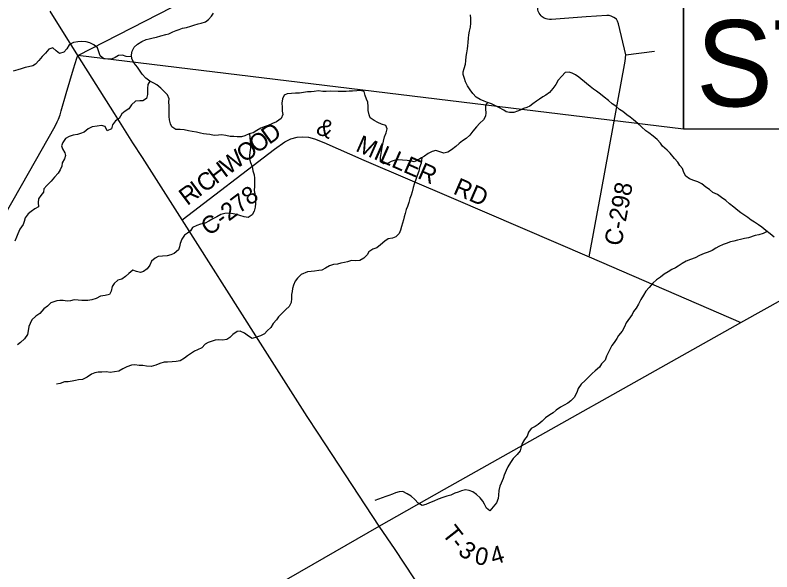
# Model space of a CAD drawing. Extents: x 0 to 34, y 0 to 22.
# Drawn here: x 5.216 to 6.445, y 18.969 to 19.874 of the extents above; entities that cross this region are included whole.
import ezdxf

# ---------------------------------------------------------------- set-up
doc = ezdxf.new("R2010")
doc.units = 0
for name, color, linetype in [('GM_X_County_Road', 7, 'Continuous'), ('GM_X_County_Road_Text', 7, 'Continuous'), ('GM_X_Minor_River', 7, 'Continuous'), ('GM_X_State_Route', 7, 'Continuous'), ('GM_X_Township_Road_Text', 7, 'Continuous'), ('SH_Text', 7, 'Continuous')]:
    doc.layers.add(name, color=color, linetype=linetype)

msp = doc.modelspace()

# ---------------------------------------------------------------- linework, layer by layer
at = {"layer": 'GM_X_County_Road'}
msp.add_line((6.2081, 19.8092), (6.2546, 19.8149), dxfattribs=at)
for points in [[(6.2081, 19.8092), (6.1961, 19.8595), (6.1942, 19.8639), (6.1925, 19.8668), (6.1885, 19.87), (6.184, 19.8721), (6.1808, 19.8729), (6.1768, 19.873), (6.1436, 19.8708), (6.087, 19.8667), (6.084, 19.8666), (6.0808, 19.8669), (6.0784, 19.8675), (6.0755, 19.8687), (6.0735, 19.8697), (6.0719, 19.8711), (6.0702, 19.8725), (6.0686, 19.8746), (6.0673, 19.8768), (6.0657, 19.8799), (6.0651, 19.8821), (6.065, 19.8831), (6.0351, 20.1202), (5.9644, 20.7031)], [(6.1482, 19.4809), (6.1678, 19.5861), (6.2068, 19.799), (6.2081, 19.8092)], [(5.4873, 19.5412), (5.6374, 19.6557), (5.6541, 19.668), (5.6638, 19.6728), (5.6742, 19.6756), (5.683, 19.6762), (5.6928, 19.6752), (5.7025, 19.6726), (5.7177, 19.6665), (5.7825, 19.6383), (5.9281, 19.5757), (6.1482, 19.4809), (6.3948, 19.3743)], [(5.2088, 18.7323), (5.2243, 18.7247), (5.2296, 18.7223), (5.2359, 18.72), (5.2413, 18.7197), (5.2468, 18.7209), (5.2521, 18.7238), (5.3175, 18.7617), (5.8075, 19.0439), (5.9136, 19.1036), (6.3948, 19.3743), (6.4657, 19.4141)]]:
    msp.add_lwpolyline(points, dxfattribs=at)
at = {"layer": 'GM_X_Minor_River'}
for points in [[(5.5171, 19.682), (5.5105, 19.6834), (5.5037, 19.6848), (5.4976, 19.6859), (5.4906, 19.6875), (5.4842, 19.6877), (5.477, 19.6878), (5.4708, 19.6924), (5.4686, 19.6971), (5.4671, 19.7038), (5.4664, 19.7089), (5.4664, 19.7136), (5.4666, 19.7188), (5.4663, 19.726), (5.4658, 19.7326), (5.4664, 19.7377), (5.4639, 19.7442), (5.4581, 19.7495), (5.4528, 19.7549), (5.4466, 19.7602), (5.4414, 19.7633), (5.435, 19.7662), (5.4284, 19.7714), (5.4224, 19.7778), (5.418, 19.7843), (5.4149, 19.7891), (5.4094, 19.7958), (5.4057, 19.8026), (5.4051, 19.8094), (5.4063, 19.8149), (5.4098, 19.8217), (5.4151, 19.8265), (5.4221, 19.831), (5.4289, 19.8341), (5.4338, 19.8352), (5.4405, 19.8367), (5.4459, 19.838), (5.4531, 19.8401), (5.4607, 19.8419), (5.4658, 19.8434), (5.4723, 19.8464), (5.4776, 19.8484), (5.4825, 19.8501), (5.488, 19.8523), (5.4946, 19.8538), (5.5016, 19.8557), (5.5065, 19.8574), (5.5132, 19.8594), (5.5183, 19.8605), (5.5251, 19.8627), (5.53, 19.8663), (5.5353, 19.872), (5.5386, 19.8769)], [(6.215, 19.7077), (6.2095, 19.7117), (6.2031, 19.7169), (6.1977, 19.7205), (6.1916, 19.7255), (6.1858, 19.7295), (6.1798, 19.7349), (6.1725, 19.7402), (6.1668, 19.7454), (6.1604, 19.75), (6.1553, 19.7532), (6.1497, 19.7578), (6.1439, 19.7626), (6.1318, 19.7729), (6.126, 19.7766), (6.1209, 19.7794), (6.116, 19.7812), (6.1094, 19.7805), (6.104, 19.7746), (6.0981, 19.768), (6.094, 19.7612), (6.0896, 19.7546), (6.0837, 19.7482), (6.0782, 19.7437), (6.0732, 19.7409), (6.0677, 19.7373), (6.063, 19.7339), (6.0569, 19.7294), (6.052, 19.726), (6.0469, 19.7236), (6.0419, 19.7219), (6.0365, 19.7195), (6.0317, 19.7174), (6.0259, 19.7153), (6.0192, 19.7153), (6.0135, 19.7167), (6.0098, 19.719), (6.0019, 19.7237), (5.9964, 19.7264), (5.9896, 19.7295), (5.983, 19.7316), (5.9781, 19.7337), (5.9715, 19.7364), (5.9649, 19.7402), (5.9597, 19.7465), (5.9552, 19.7524), (5.9507, 19.7589), (5.9477, 19.7654), (5.9458, 19.7705), (5.944, 19.777), (5.9438, 19.7817), (5.9452, 19.787), (5.9473, 19.794), (5.9483, 19.7995), (5.9487, 19.8062), (5.9495, 19.8122), (5.9508, 19.8189), (5.9514, 19.8236), (5.952, 19.8293), (5.9524, 19.8361), (5.953, 19.8416), (5.9542, 19.8477), (5.9554, 19.8541), (5.956, 19.8607), (5.956, 19.8681), (5.9555, 19.874)], [(5.4054, 19.8061), (5.3968, 19.8065), (5.3908, 19.8088), (5.3842, 19.8083), (5.3788, 19.8049), (5.3739, 19.8026), (5.3673, 19.8019), (5.3601, 19.8029), (5.3545, 19.8073), (5.3523, 19.8138), (5.35, 19.8204), (5.3442, 19.8254), (5.3378, 19.8285), (5.3314, 19.83), (5.3244, 19.8308), (5.3179, 19.8301), (5.3109, 19.8292), (5.3041, 19.8253), (5.3001, 19.819), (5.2954, 19.8132), (5.2882, 19.8111), (5.2829, 19.8159), (5.2776, 19.8203), (5.2708, 19.8185), (5.2653, 19.8121), (5.26, 19.8062), (5.2545, 19.7998), (5.2495, 19.7939), (5.2448, 19.7915), (5.2381, 19.7895), (5.2328, 19.7884), (5.2258, 19.7865), (5.2204, 19.785), (5.2133, 19.7824)], [(5.4352, 19.7661), (5.4315, 19.7609), (5.4311, 19.7547), (5.4311, 19.7499), (5.4312, 19.7448), (5.4295, 19.7383), (5.4238, 19.7342), (5.4185, 19.7342), (5.4117, 19.7339), (5.4051, 19.7281), (5.4011, 19.7216), (5.395, 19.7179), (5.3895, 19.7134), (5.3853, 19.7058), (5.3792, 19.7019), (5.3745, 19.6955), (5.3725, 19.6888), (5.3659, 19.6858), (5.3625, 19.6925), (5.3563, 19.6942), (5.3493, 19.6933), (5.3414, 19.6924), (5.3351, 19.6887), (5.3281, 19.6834), (5.3222, 19.6816), (5.3173, 19.6795), (5.3107, 19.6784), (5.3039, 19.6766), (5.2982, 19.6732), (5.2936, 19.6666), (5.2917, 19.6615), (5.2933, 19.6565), (5.2969, 19.6502), (5.2982, 19.6455), (5.2965, 19.6404), (5.2928, 19.6336), (5.2922, 19.6283), (5.2896, 19.6222), (5.2861, 19.6169), (5.2804, 19.6105), (5.2745, 19.6041), (5.2679, 19.5971), (5.2631, 19.5913), (5.2621, 19.586), (5.2582, 19.5805), (5.254, 19.5754), (5.2537, 19.5691), (5.2543, 19.5625), (5.2482, 19.5591), (5.2423, 19.5546), (5.2376, 19.551), (5.2328, 19.5442), (5.2309, 19.5384), (5.2292, 19.5334), (5.224, 19.5261), (5.2204, 19.5185), (5.2183, 19.5132), (5.216, 19.5064)], [(5.9832, 19.7315), (5.9802, 19.7276), (5.9798, 19.721), (5.9803, 19.7149), (5.9799, 19.7096), (5.9765, 19.7037), (5.9708, 19.6983), (5.9654, 19.6921), (5.9595, 19.6854), (5.9544, 19.6787), (5.9487, 19.673), (5.9426, 19.6694), (5.9375, 19.6651), (5.9316, 19.66), (5.925, 19.6548), (5.9189, 19.651), (5.9121, 19.6497), (5.906, 19.6518), (5.8996, 19.6538), (5.8936, 19.6523), (5.8869, 19.6491), (5.8809, 19.6446), (5.8761, 19.6418), (5.8691, 19.6373), (5.8644, 19.6354), (5.8583, 19.637), (5.8527, 19.6376), (5.8451, 19.6382), (5.8383, 19.6386), (5.8317, 19.6373), (5.8268, 19.6357), (5.822, 19.6332), (5.815, 19.6319), (5.8094, 19.6354), (5.8094, 19.6422), (5.8106, 19.6488), (5.8116, 19.6553), (5.8129, 19.6619), (5.8145, 19.6691), (5.8158, 19.6759), (5.8187, 19.6827), (5.8203, 19.689), (5.818, 19.6941), (5.8114, 19.6964), (5.8052, 19.699), (5.799, 19.7024), (5.7926, 19.7068), (5.7909, 19.7116), (5.7894, 19.7188), (5.7895, 19.7254), (5.7889, 19.7323), (5.7869, 19.737), (5.7847, 19.7433), (5.7832, 19.7497), (5.7764, 19.7513), (5.7711, 19.7506), (5.7639, 19.7499), (5.7588, 19.7501), (5.7539, 19.7495), (5.7478, 19.7498), (5.7407, 19.7498), (5.7278, 19.7499), (5.7214, 19.7498), (5.7157, 19.7498), (5.7089, 19.7504), (5.7019, 19.7495), (5.697, 19.749), (5.6909, 19.7488), (5.6843, 19.7477), (5.6779, 19.747), (5.6713, 19.747), (5.6649, 19.7465), (5.6582, 19.7458), (5.6533, 19.7437), (5.6503, 19.7379), (5.6493, 19.7309), (5.65, 19.7244), (5.6501, 19.7174), (5.6509, 19.7125), (5.6482, 19.7056), (5.6406, 19.7004), (5.634, 19.6974), (5.627, 19.6946), (5.6222, 19.6925), (5.6152, 19.6903), (5.6088, 19.6864), (5.6025, 19.6822), (5.5963, 19.6806), (5.5891, 19.6776), (5.5838, 19.6761), (5.577, 19.6758), (5.5711, 19.6767), (5.5654, 19.6766), (5.5586, 19.6781), (5.5515, 19.6791), (5.5464, 19.6788), (5.5394, 19.6783), (5.5322, 19.6795), (5.5271, 19.6801), (5.5222, 19.681), (5.5171, 19.682)], [(6.4488, 19.5131), (6.442, 19.5186), (6.4353, 19.524), (6.4285, 19.5292), (6.4234, 19.5328), (6.4168, 19.5374), (6.4116, 19.5408), (6.4061, 19.5449), (6.3997, 19.5495), (6.3948, 19.5527), (6.3899, 19.5565), (6.3833, 19.5617), (6.3764, 19.5669), (6.37, 19.5728), (6.3634, 19.5774), (6.3566, 19.5822), (6.3492, 19.5854), (6.3438, 19.5904), (6.3378, 19.5944), (6.3312, 19.5994), (6.3248, 19.6027), (6.3182, 19.6052), (6.3114, 19.6077), (6.3054, 19.6119), (6.3022, 19.6182), (6.2998, 19.6245), (6.2958, 19.6292), (6.2921, 19.6346), (6.2868, 19.6409), (6.2799, 19.6492), (6.2748, 19.6542), (6.2675, 19.6607), (6.2641, 19.6657), (6.2586, 19.6718), (6.2522, 19.6771), (6.2453, 19.6823), (6.2404, 19.6857), (6.2334, 19.6924), (6.2272, 19.6976), (6.2203, 19.7037), (6.215, 19.7077)], [(5.5968, 19.6807), (5.5974, 19.6747), (5.5981, 19.6686), (5.5982, 19.6639), (5.5982, 19.6578), (5.5976, 19.6506), (5.597, 19.6457), (5.5968, 19.6402), (5.5983, 19.6341), (5.6009, 19.6276), (5.6022, 19.6208), (5.6042, 19.6141), (5.6051, 19.609), (5.6051, 19.6025), (5.6047, 19.5957), (5.6046, 19.5889), (5.6054, 19.5834), (5.6063, 19.5784), (5.6066, 19.5729), (5.6066, 19.5678), (5.6062, 19.5619), (5.6043, 19.5555), (5.6014, 19.5491), (5.5946, 19.5449), (5.5879, 19.5461), (5.5813, 19.5484), (5.5759, 19.5496), (5.5702, 19.551), (5.5642, 19.552), (5.5566, 19.5516), (5.55, 19.5498), (5.5435, 19.546), (5.5373, 19.5428), (5.5306, 19.5391), (5.5246, 19.5359), (5.5174, 19.5339), (5.5111, 19.5322), (5.5043, 19.5285), (5.5009, 19.5235), (5.4961, 19.5196), (5.491, 19.5164), (5.4868, 19.51), (5.4843, 19.5028), (5.4832, 19.4973), (5.4816, 19.4924), (5.4746, 19.4865), (5.4691, 19.4841), (5.463, 19.4828), (5.4553, 19.4821), (5.4483, 19.4816), (5.4436, 19.4791), (5.4379, 19.4739), (5.4352, 19.4678), (5.4306, 19.4616), (5.4247, 19.4574), (5.4198, 19.4554), (5.4132, 19.4573), (5.4072, 19.4595), (5.4011, 19.4538), (5.3956, 19.4491), (5.3895, 19.4446), (5.3829, 19.4433), (5.3768, 19.438), (5.3739, 19.4329), (5.3722, 19.4252), (5.3695, 19.4199), (5.3627, 19.418), (5.3548, 19.4173), (5.3479, 19.4134), (5.3409, 19.4111), (5.3345, 19.41), (5.3296, 19.4099), (5.3247, 19.4101), (5.3184, 19.4109), (5.3122, 19.4111), (5.3062, 19.4096), (5.301, 19.4089), (5.2941, 19.4099), (5.2891, 19.4101), (5.2842, 19.4094), (5.2791, 19.4081), (5.2742, 19.4064), (5.2687, 19.4011), (5.263, 19.3964), (5.2565, 19.3891), (5.2499, 19.3848), (5.2434, 19.3785), (5.2404, 19.3729), (5.2384, 19.3678), (5.2375, 19.3611), (5.2363, 19.3549), (5.2313, 19.3479), (5.2251, 19.3417), (5.2203, 19.3381)], [(5.8767, 19.6421), (5.8753, 19.6331), (5.873, 19.6263), (5.8717, 19.6204), (5.8692, 19.6134), (5.8669, 19.6066), (5.8644, 19.599), (5.8628, 19.5937), (5.8611, 19.5869), (5.8592, 19.5814), (5.8574, 19.5759), (5.8557, 19.5695), (5.8534, 19.563), (5.8513, 19.5581), (5.8494, 19.5515), (5.8478, 19.5462), (5.8467, 19.5413), (5.8453, 19.5358), (5.8438, 19.5303), (5.8422, 19.5246), (5.8397, 19.5187), (5.8342, 19.5138), (5.8289, 19.5116), (5.8221, 19.5101), (5.8164, 19.5064), (5.8096, 19.5003), (5.8037, 19.4958), (5.7972, 19.4934), (5.7904, 19.4893), (5.7879, 19.4843), (5.7822, 19.4787), (5.7762, 19.4749), (5.7688, 19.4744), (5.7624, 19.475), (5.7561, 19.4732), (5.7512, 19.4721), (5.7453, 19.4708), (5.7397, 19.4693), (5.7332, 19.4684), (5.7268, 19.4663), (5.7203, 19.4628), (5.7145, 19.4596), (5.7092, 19.4587), (5.7024, 19.458), (5.6967, 19.4574), (5.691, 19.4565), (5.6806, 19.4524), (5.6747, 19.4464), (5.6709, 19.4413), (5.6682, 19.435), (5.6667, 19.4297), (5.6659, 19.425), (5.6651, 19.4201), (5.6651, 19.4136), (5.6643, 19.4068), (5.6612, 19.4004), (5.6559, 19.3953), (5.6496, 19.3894), (5.6439, 19.3838), (5.6405, 19.3787), (5.6354, 19.3728), (5.6312, 19.3664), (5.6255, 19.3609), (5.6211, 19.356), (5.6147, 19.353), (5.608, 19.3504), (5.601, 19.3482), (5.5954, 19.3524), (5.5888, 19.3572), (5.5818, 19.3605), (5.5769, 19.3597), (5.5695, 19.3548), (5.5647, 19.3501), (5.56, 19.3468), (5.5532, 19.3458), (5.546, 19.3465), (5.5409, 19.3459), (5.536, 19.3439), (5.5297, 19.342), (5.525, 19.3394), (5.5195, 19.3335), (5.5125, 19.3302), (5.5077, 19.3279), (5.5024, 19.3245), (5.4962, 19.3204), (5.491, 19.3165), (5.4842, 19.3121), (5.4776, 19.311), (5.4715, 19.3105), (5.4634, 19.3102), (5.4583, 19.31), (5.4511, 19.308), (5.4445, 19.305), (5.4369, 19.3031), (5.4295, 19.3034), (5.4235, 19.3044), (5.4174, 19.3046), (5.4105, 19.3054), (5.405, 19.3049), (5.3978, 19.3024), (5.3913, 19.2989)], [(6.4375, 19.5223), (6.4311, 19.5189), (6.4239, 19.5169), (6.4178, 19.5159), (6.4072, 19.5118), (6.4008, 19.5106), (6.3942, 19.5091), (6.3893, 19.508), (6.383, 19.5067), (6.3777, 19.5052), (6.3707, 19.5026), (6.3658, 19.5011), (6.359, 19.4981), (6.3542, 19.4953), (6.348, 19.4914), (6.3417, 19.4884), (6.3349, 19.4863), (6.3277, 19.4831), (6.3203, 19.4796), (6.3129, 19.4768), (6.3061, 19.474), (6.2993, 19.4702), (6.293, 19.4661), (6.2883, 19.4633), (6.2826, 19.4603), (6.2765, 19.4569), (6.2703, 19.4528), (6.264, 19.4483), (6.2576, 19.4436), (6.2519, 19.4385), (6.2456, 19.4313), (6.2406, 19.4251), (6.2366, 19.4187), (6.2324, 19.4115), (6.2286, 19.4043), (6.2246, 19.3977), (6.2202, 19.3924), (6.2181, 19.3873), (6.2086, 19.3741), (6.2055, 19.3675), (6.2017, 19.3601), (6.1962, 19.3533), (6.1933, 19.3484), (6.1891, 19.342), (6.1851, 19.3369), (6.1819, 19.3308), (6.179, 19.325), (6.1765, 19.3199), (6.1744, 19.313), (6.1685, 19.3072), (6.1651, 19.3017), (6.1583, 19.2959), (6.1531, 19.2916), (6.1467, 19.285), (6.1417, 19.2804), (6.1356, 19.274), (6.1305, 19.2674), (6.1286, 19.2625), (6.1265, 19.2576), (6.124, 19.2527), (6.1185, 19.247), (6.1136, 19.2434), (6.1075, 19.2399), (6.102, 19.2367), (6.0948, 19.2318), (6.09, 19.2279), (6.0845, 19.2243), (6.0775, 19.2194), (6.0718, 19.2139), (6.0654, 19.209), (6.0604, 19.2055), (6.0542, 19.2025), (6.0496, 19.1961), (6.0475, 19.1896), (6.0433, 19.1845), (6.0395, 19.1777), (6.0381, 19.1726), (6.0362, 19.1658), (6.0312, 19.1598), (6.0252, 19.1535), (6.0204, 19.1471), (6.0164, 19.1401), (6.0133, 19.1341), (6.0103, 19.1263), (6.0085, 19.1212), (6.0053, 19.1135), (6.0035, 19.1084), (6.0016, 19.1015), (6.001, 19.0941), (6.0008, 19.0888), (5.9977, 19.0815), (5.9922, 19.0752), (5.9869, 19.0684), (5.9816, 19.0728), (5.9786, 19.0795), (5.9756, 19.0843), (5.9713, 19.0898), (5.9653, 19.0948), (5.9596, 19.0993), (5.9536, 19.1015), (5.9474, 19.1026)], [(5.3913, 19.2989), (5.3845, 19.2955), (5.3777, 19.2944), (5.3705, 19.2933), (5.3647, 19.2941), (5.3573, 19.2936), (5.3512, 19.2936), (5.3459, 19.2927), (5.3401, 19.2903), (5.3334, 19.2854), (5.3259, 19.2818), (5.3194, 19.2815), (5.3143, 19.2804), (5.3088, 19.2791), (5.3024, 19.278), (5.2963, 19.2779), (5.2895, 19.2754), (5.2833, 19.274)], [(5.9474, 19.1026), (5.9408, 19.1008), (5.9356, 19.0987), (5.93, 19.0971), (5.9235, 19.0939), (5.9173, 19.0926), (5.9105, 19.09), (5.9029, 19.0876), (5.8961, 19.084), (5.8892, 19.0816), (5.883, 19.0786), (5.8771, 19.0773), (5.8707, 19.0811), (5.8655, 19.0869), (5.8591, 19.0924), (5.8527, 19.0964), (5.8459, 19.0997), (5.8398, 19.0993), (5.8338, 19.0977), (5.829, 19.0958), (5.8233, 19.0934), (5.8184, 19.0917), (5.8122, 19.0899), (5.8001, 19.0854)]]:
    msp.add_lwpolyline(points, dxfattribs=at)
at = {"layer": 'GM_X_State_Route'}
msp.add_line((5.3182, 19.808), (5.273, 19.8803), dxfattribs=at)
for points in [[(5.1997, 19.5495), (5.2382, 19.6171), (5.281, 19.6932), (5.2847, 19.7001), (5.2866, 19.7047), (5.2892, 19.7118), (5.2911, 19.7183), (5.2992, 19.7465), (5.3108, 19.7865), (5.3162, 19.8035), (5.3182, 19.808)], [(5.8795, 18.9357), (5.8334, 19.0056), (5.8075, 19.0439), (5.7083, 19.1948), (5.6903, 19.2218), (5.6072, 19.3527), (5.4873, 19.5412), (5.4229, 19.6423), (5.4075, 19.6664), (5.3775, 19.714), (5.3182, 19.808)]]:
    msp.add_lwpolyline(points, dxfattribs=at)
at = {"layer": 'SH_Text'}
msp.add_lwpolyline([(6.3016, 19.6886), (5.3182, 19.808), (6.3016, 20.3124)], close=True, dxfattribs=at)
msp.add_lwpolyline([(8.1244, 20.0434), (8.1244, 19.6886), (6.3016, 19.6886), (6.3016, 20.3124), (8.1244, 20.3124), (8.1244, 20.053)], dxfattribs=at)

# ---------------------------------------------------------------- texts
at = {"layer": 'GM_X_County_Road_Text'}
for s, height, rotation, p in [('&', 0.0284, 337.3786, (5.7029, 19.6818)), ('D', 0.0284, 35.6757, (5.6289, 19.6626)), ('O', 0.0284, 36.6972, (5.6089, 19.6478)), ('MILLER', 0.02841, 336.2251, (5.7676, 19.6536)), ('O', 0.0284, 36.7133, (5.5889, 19.6328)), ('W', 0.0284, 36.7133, (5.5625, 19.6131)), ('H', 0.0284, 36.7163, (5.5425, 19.5982)), ('C', 0.0284, 36.7138, (5.5238, 19.5842)), ('I', 0.0284, 36.7138, (5.5144, 19.5773)), ('RD', 0.02841, 336.5401, (5.926, 19.5842)), ('C-298', 0.02841, 79.4979, (6.2005, 19.4975)), ('R', 0.0284, 36.7138, (5.4957, 19.5633)), ('C-278', 0.02841, 36.815, (5.5311, 19.514))]:
    msp.add_text(s, height=height, rotation=rotation, dxfattribs=at).set_placement(p)
at = {"layer": 'GM_X_Township_Road_Text'}
for s, rotation, p in [('T', 308.024, (5.9083, 19.0311)), ('-', 308.024, (5.9213, 19.0143)), ('3', 321.7099, (5.9337, 18.9999)), ('0', 349.0818, (5.9608, 18.9829)), ('4', 16.4537, (5.9926, 18.9803))]:
    msp.add_text(s, height=0.0284, rotation=rotation, dxfattribs=at).set_placement(p)
at = {"layer": 'SH_Text'}
msp.add_text('STA. 745+99.17', height=0.14, dxfattribs=at).set_placement((6.3218, 19.7254))

doc.saveas('drawing.dxf')
